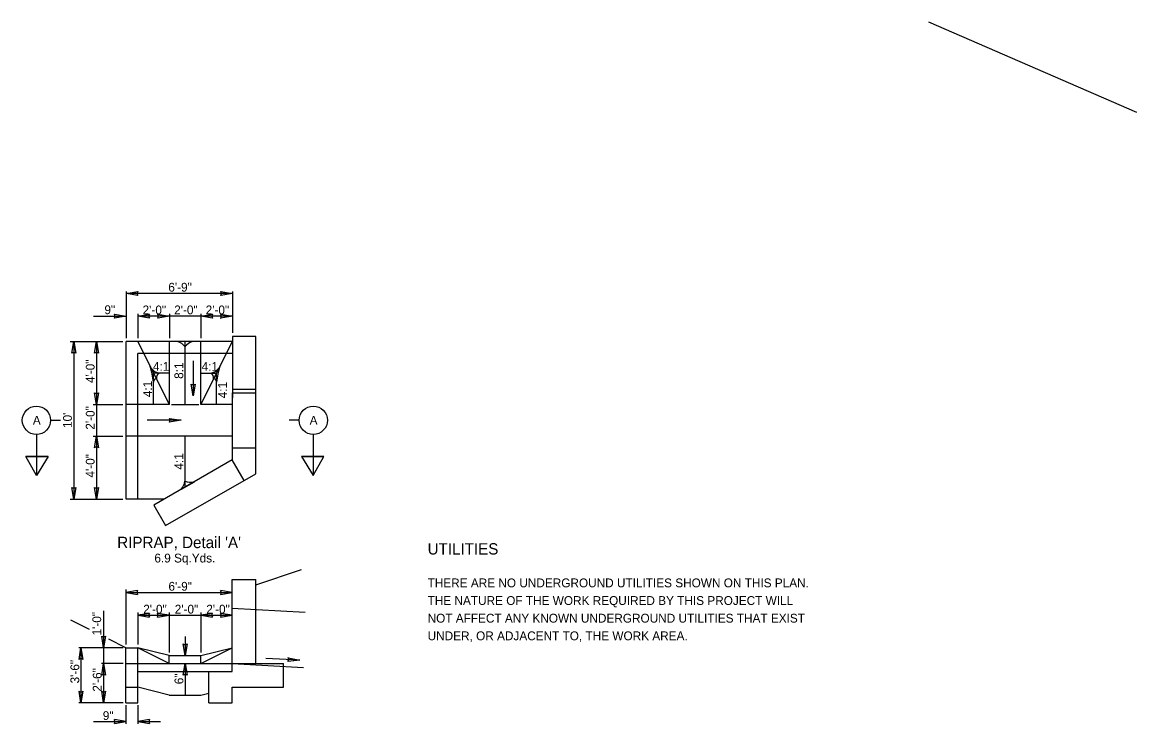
# Model space of a CAD drawing. Extents: x -30 to 76, y -31 to 50.
# Drawn here: x -18.16 to -0.47, y 38.43 to 49.56 of the extents above; entities that cross this region are included whole.
import ezdxf

# ---------------------------------------------------------------- set-up
doc = ezdxf.new("R2010")
doc.units = 0
for name, color, linetype in [('BR_P_Gen_Text', 7, 'Continuous'), ('Default', 7, 'Continuous'), ('DR_Gutter', 7, 'Continuous'), ('DR_P_Culvert', 7, 'Continuous'), ('DR_P_Headwall', 7, 'Continuous'), ('DT_P_Slope_Break_Line', 7, 'Continuous'), ('GK_Drainage_Nodes', 7, 'Continuous'), ('SH_Data', 7, 'Continuous'), ('SH_Text', 7, 'Continuous'), ('TX_X_1', 7, 'Continuous'), ('XS_P_Finished_Grade', 7, 'Continuous')]:
    doc.layers.add(name, color=color, linetype=linetype)

msp = doc.modelspace()

# ---------------------------------------------------------------- linework, layer by layer
at = {"layer": 'BR_P_Gen_Text'}
for p, q in [((-17.713, 43.246), (-17.558, 43.246)), ((-13.767, 43.246), (-13.923, 43.246)), ((-17.938, 43.021), (-17.938, 42.37)), ((-13.542, 43.021), (-13.542, 42.37)), ((-18.104, 42.67), (-17.749, 42.67)), ((-17.938, 42.37), (-18.104, 42.67)), ((-18.104, 42.67), (-17.749, 42.67)), ((-17.749, 42.67), (-18.104, 42.67)), ((-18.104, 42.67), (-17.749, 42.67)), ((-17.938, 42.37), (-18.104, 42.67)), ((-17.749, 42.67), (-17.938, 42.37)), ((-17.749, 42.67), (-17.938, 42.37)), ((-13.376, 42.67), (-13.731, 42.67)), ((-13.731, 42.67), (-13.542, 42.37)), ((-13.376, 42.67), (-13.731, 42.67)), ((-13.731, 42.67), (-13.376, 42.67)), ((-13.376, 42.67), (-13.731, 42.67)), ((-13.731, 42.67), (-13.542, 42.37)), ((-13.542, 42.37), (-13.376, 42.67)), ((-13.542, 42.37), (-13.376, 42.67))]:
    msp.add_line(p, q, dxfattribs=at)
for centre in [(-17.938, 43.246), (-13.542, 43.246)]:
    msp.add_circle(centre, 0.225, dxfattribs=at)
at = {"layer": 'Default'}
for p, q in [((-16.515, 45.258), (-16.329, 45.288)), ((-16.33, 45.227), (-16.515, 45.258)), ((-16.33, 45.227), (-16.33, 45.227)), ((-16.329, 45.288), (-16.329, 45.288)), ((-14.825, 45.258), (-15.011, 45.227)), ((-15.011, 45.227), (-15.01, 45.227)), ((-15.01, 45.288), (-15.01, 45.288)), ((-15.01, 45.288), (-14.825, 45.258)), ((-16.515, 44.898), (-16.7, 44.867)), ((-16.7, 44.867), (-16.7, 44.867)), ((-16.699, 44.928), (-16.699, 44.928)), ((-16.699, 44.928), (-16.515, 44.898)), ((-16.329, 44.898), (-16.143, 44.928)), ((-16.144, 44.867), (-16.329, 44.898)), ((-16.143, 44.928), (-16.144, 44.928)), ((-16.144, 44.867), (-16.144, 44.867)), ((-15.827, 44.898), (-16.013, 44.867)), ((-16.013, 44.867), (-16.012, 44.867)), ((-16.012, 44.928), (-16.012, 44.928)), ((-16.012, 44.928), (-15.827, 44.898)), ((-15.327, 44.898), (-15.142, 44.928)), ((-15.142, 44.867), (-15.327, 44.898)), ((-15.142, 44.928), (-15.142, 44.928)), ((-15.142, 44.867), (-15.142, 44.867)), ((-14.827, 44.898), (-15.013, 44.867)), ((-15.013, 44.867), (-15.012, 44.867)), ((-15.012, 44.928), (-15.012, 44.928)), ((-15.012, 44.928), (-14.827, 44.898)), ((-17.375, 44.311), (-17.345, 44.496)), ((-17.345, 44.496), (-17.314, 44.31)), ((-17.015, 44.311), (-16.985, 44.496)), ((-16.985, 44.496), (-16.954, 44.31)), ((-17.375, 44.311), (-17.375, 44.311)), ((-17.314, 44.31), (-17.314, 44.31)), ((-17.015, 44.311), (-17.015, 44.311)), ((-16.954, 44.31), (-16.954, 44.31)), ((-15.451, 43.636), (-15.482, 43.821)), ((-15.482, 43.821), (-15.482, 43.821)), ((-15.42, 43.821), (-15.451, 43.636)), ((-15.42, 43.821), (-15.42, 43.821)), ((-16.985, 43.496), (-17.015, 43.681)), ((-17.015, 43.681), (-17.015, 43.681)), ((-16.954, 43.681), (-16.985, 43.496)), ((-16.954, 43.681), (-16.954, 43.681)), ((-15.642, 43.246), (-15.828, 43.215)), ((-15.828, 43.215), (-15.828, 43.215)), ((-15.827, 43.277), (-15.827, 43.277)), ((-15.827, 43.277), (-15.642, 43.246)), ((-17.015, 42.811), (-16.985, 42.996)), ((-16.985, 42.996), (-16.954, 42.81)), ((-17.015, 42.811), (-17.015, 42.811)), ((-16.954, 42.81), (-16.954, 42.81)), ((-17.345, 41.996), (-17.375, 42.181)), ((-17.375, 42.181), (-17.375, 42.181)), ((-17.314, 42.181), (-17.345, 41.996)), ((-17.314, 42.181), (-17.314, 42.181)), ((-16.985, 41.996), (-17.015, 42.181)), ((-17.015, 42.181), (-17.015, 42.181)), ((-16.954, 42.181), (-16.985, 41.996)), ((-16.954, 42.181), (-16.954, 42.181)), ((-16.333, 40.543), (-16.518, 40.512)), ((-16.333, 40.543), (-16.333, 40.543)), ((-14.828, 40.512), (-15.014, 40.543)), ((-15.014, 40.543), (-15.014, 40.543)), ((-16.518, 40.512), (-16.332, 40.481)), ((-16.332, 40.481), (-16.332, 40.481)), ((-15.013, 40.481), (-14.828, 40.512)), ((-15.013, 40.481), (-15.013, 40.481)), ((-16.145, 40.183), (-16.33, 40.152)), ((-16.145, 40.183), (-16.145, 40.183)), ((-15.83, 40.152), (-16.016, 40.183)), ((-16.016, 40.183), (-16.016, 40.183)), ((-15.145, 40.183), (-15.33, 40.152)), ((-15.145, 40.183), (-15.145, 40.183)), ((-14.828, 40.152), (-15.014, 40.183)), ((-15.014, 40.183), (-15.014, 40.183)), ((-16.33, 40.152), (-16.145, 40.121)), ((-16.145, 40.121), (-16.145, 40.121)), ((-16.015, 40.121), (-15.83, 40.152)), ((-16.015, 40.121), (-16.015, 40.121)), ((-15.33, 40.152), (-15.145, 40.121)), ((-15.145, 40.121), (-15.145, 40.121)), ((-15.013, 40.121), (-14.828, 40.152)), ((-15.013, 40.121), (-15.013, 40.121)), ((-16.871, 39.637), (-16.902, 39.823)), ((-16.902, 39.823), (-16.902, 39.823)), ((-16.84, 39.822), (-16.871, 39.637)), ((-16.84, 39.822), (-16.84, 39.822)), ((-17.261, 39.452), (-17.231, 39.637)), ((-17.231, 39.637), (-17.2, 39.452)), ((-15.578, 39.512), (-15.609, 39.698)), ((-15.609, 39.698), (-15.609, 39.698)), ((-15.547, 39.697), (-15.578, 39.512)), ((-15.547, 39.697), (-15.547, 39.697)), ((-13.94, 39.479), (-13.94, 39.479)), ((-13.94, 39.479), (-13.757, 39.439)), ((-17.261, 39.452), (-17.261, 39.452)), ((-17.2, 39.452), (-17.2, 39.452)), ((-16.902, 39.202), (-16.871, 39.387)), ((-16.871, 39.387), (-16.84, 39.202)), ((-15.609, 39.202), (-15.578, 39.387)), ((-15.578, 39.387), (-15.547, 39.202)), ((-13.757, 39.439), (-13.944, 39.418)), ((-13.944, 39.418), (-13.944, 39.418)), ((-16.902, 39.202), (-16.902, 39.202)), ((-16.84, 39.202), (-16.84, 39.202)), ((-15.609, 39.202), (-15.609, 39.202)), ((-15.547, 39.202), (-15.547, 39.202)), ((-17.231, 38.762), (-17.261, 38.948)), ((-17.261, 38.948), (-17.261, 38.948)), ((-17.2, 38.947), (-17.231, 38.762)), ((-17.2, 38.947), (-17.2, 38.947)), ((-16.871, 38.762), (-16.902, 38.948)), ((-16.902, 38.948), (-16.902, 38.948)), ((-16.84, 38.947), (-16.871, 38.762)), ((-16.84, 38.947), (-16.84, 38.947)), ((-16.516, 38.466), (-16.701, 38.497)), ((-16.701, 38.497), (-16.701, 38.497)), ((-16.701, 38.435), (-16.516, 38.466)), ((-16.701, 38.435), (-16.701, 38.435)), ((-16.143, 38.497), (-16.328, 38.466)), ((-16.328, 38.466), (-16.143, 38.435)), ((-16.143, 38.497), (-16.143, 38.497)), ((-16.143, 38.435), (-16.143, 38.435))]:
    msp.add_line(p, q, dxfattribs=at)
for centre, start, end in [((-16.282, 45.257), 146.178, 212.8588), ((-15.057, 45.258), 326.178, 32.8588), ((-16.747, 44.898), 326.178, 32.8588), ((-16.097, 44.897), 146.178, 212.8588), ((-16.059, 44.898), 326.178, 32.8588), ((-15.095, 44.897), 146.178, 212.8588), ((-15.059, 44.898), 326.178, 32.8588), ((-17.345, 44.264), 56.178, 122.8588), ((-16.985, 44.264), 56.178, 122.8588), ((-15.451, 43.868), 236.178, 302.8588), ((-16.984, 43.728), 236.178, 302.8588), ((-15.874, 43.246), 326.178, 32.8588), ((-16.985, 42.764), 56.178, 122.8588), ((-17.344, 42.228), 236.178, 302.8588), ((-16.984, 42.228), 236.178, 302.8588), ((-16.285, 40.513), 147.1412, 213.822), ((-15.06, 40.512), 327.1412, 33.822), ((-16.098, 40.153), 147.1412, 213.822), ((-16.062, 40.152), 327.1412, 33.822), ((-15.098, 40.153), 147.1412, 213.822), ((-15.06, 40.152), 327.1412, 33.822), ((-16.87, 39.869), 236.178, 302.8588), ((-15.578, 39.744), 236.178, 302.8588), ((-17.231, 39.405), 56.178, 122.8588), ((-13.989, 39.452), 323.0985, 29.7792), ((-16.871, 39.155), 56.178, 122.8588), ((-15.579, 39.155), 56.178, 122.8588), ((-17.23, 38.994), 236.178, 302.8588), ((-16.87, 38.994), 236.178, 302.8588), ((-16.748, 38.466), 327.1412, 33.822), ((-16.096, 38.466), 147.1412, 213.822)]:
    msp.add_arc(centre, 0.0563, start, end, dxfattribs=at)
at = {"layer": 'DR_Gutter'}
for p, q in [((-14.827, 44.496), (-16.515, 44.496)), ((-16.515, 41.996), (-16.515, 44.496)), ((-15.827, 43.496), (-16.327, 44.496)), ((-15.827, 43.496), (-15.827, 44.496)), ((-15.327, 43.496), (-15.327, 44.496)), ((-15.327, 43.496), (-14.827, 44.496)), ((-16.327, 41.996), (-16.327, 44.308)), ((-14.827, 44.308), (-16.327, 44.308)), ((-15.827, 43.496), (-16.515, 43.496)), ((-15.794, 43.496), (-15.359, 43.496)), ((-14.827, 43.496), (-15.327, 43.496)), ((-14.827, 42.996), (-16.515, 42.996)), ((-15.905, 41.996), (-16.515, 41.996)), ((-16.516, 39.637), (-16.328, 39.637)), ((-16.516, 39.387), (-16.516, 39.637)), ((-15.828, 39.387), (-16.328, 39.637)), ((-15.828, 39.512), (-16.328, 39.637)), ((-16.328, 39.262), (-16.328, 39.637)), ((-15.328, 39.387), (-14.828, 39.637)), ((-15.328, 39.512), (-14.828, 39.637)), ((-15.828, 39.512), (-15.328, 39.512)), ((-15.828, 39.387), (-15.828, 39.512)), ((-15.328, 39.387), (-15.328, 39.512)), ((-16.516, 38.762), (-16.516, 39.387)), ((-16.516, 39.387), (-14.828, 39.387)), ((-16.328, 39.262), (-15.203, 39.262)), ((-16.328, 38.762), (-16.328, 39.262)), ((-16.516, 39.012), (-16.328, 39.012)), ((-15.828, 38.887), (-16.328, 39.012)), ((-16.516, 38.762), (-16.328, 38.762)), ((-15.828, 38.887), (-15.328, 38.887)), ((-15.328, 38.887), (-15.203, 38.918))]:
    msp.add_line(p, q, dxfattribs=at)
at = {"layer": 'DR_P_Culvert'}
for p, q in [((-14.827, 43.683), (-14.452, 43.683)), ((-14.827, 42.808), (-14.827, 43.683)), ((-14.827, 42.808), (-14.452, 42.808)), ((-14.828, 39.387), (-14.828, 40.263)), ((-14.828, 40.263), (-13.671, 40.201)), ((-14.828, 39.387), (-13.696, 39.326))]:
    msp.add_line(p, q, dxfattribs=at)
at = {"layer": 'DR_P_Headwall'}
for p, q in [((-0.469, 48.128), (-3.771, 49.561)), ((-14.826, 43.741), (-14.451, 43.74)), ((-14.641, 42.291), (-14.828, 42.616)), ((-14.828, 40.721), (-14.453, 40.721)), ((-14.828, 40.263), (-14.828, 40.721)), ((-14.453, 40.243), (-14.453, 40.721)), ((-14.453, 39.387), (-14.453, 40.243)), ((-14.828, 39.387), (-14.016, 39.387)), ((-14.828, 39.262), (-14.828, 39.387)), ((-14.016, 39.344), (-14.016, 39.387)), ((-14.016, 39.012), (-14.016, 39.344)), ((-15.203, 38.762), (-15.203, 39.262)), ((-15.203, 39.262), (-14.828, 39.262)), ((-14.828, 38.762), (-14.828, 39.012)), ((-14.828, 39.012), (-14.016, 39.012)), ((-15.203, 38.762), (-14.828, 38.762))]:
    msp.add_line(p, q, dxfattribs=at)
msp.add_lwpolyline([(-14.453, 44.573), (-14.825, 44.574), (-14.828, 42.616), (-16.074, 41.899), (-15.888, 41.576), (-14.453, 42.399)], close=True, dxfattribs=at)
at = {"layer": 'DT_P_Slope_Break_Line'}
for p, q in [((-15.461, 44.496), (-15.697, 44.496)), ((-15.579, 43.496), (-15.579, 44.496)), ((-16.077, 43.496), (-16.077, 43.996)), ((-15.827, 43.996), (-16.077, 43.996)), ((-15.327, 43.996), (-15.077, 43.996)), ((-15.077, 43.496), (-15.077, 43.996)), ((-15.579, 42.183), (-15.579, 42.996)), ((-15.435, 42.266), (-15.64, 42.148))]:
    msp.add_line(p, q, dxfattribs=at)
for centre, radius, start, end in [((-15.791, 44.236), 0.277, 39.9236, 69.9953), ((-15.367, 44.236), 0.277, 110.0047, 140.0764), ((-15.96, 44.188), 0.195, 206.9477, 261.6468), ((-17.184, 43.75), 1.108, 5.2948, 18.4424), ((-15.198, 44.188), 0.195, 278.3532, 333.0523), ((-13.974, 43.75), 1.108, 161.5576, 174.7052), ((-16.029, 43.85), 0.0518, 95.3314, 178.1507), ((-15.944, 43.916), 0.091, 118.8267, 188.9727), ((-15.214, 43.916), 0.091, 351.0273, 61.1733), ((-15.129, 43.85), 0.0518, 1.8493, 84.6686), ((-15.852, 42.327), 0.277, 319.7568, 349.994), ((-15.483, 42.539), 0.277, 249.8412, 280.0783)]:
    msp.add_arc(centre, radius, start, end, dxfattribs=at)
at = {"layer": 'GK_Drainage_Nodes'}
for p, q in [((-14.83, 43.246), (-14.83, 43.246)), ((-14.83, 43.246), (-14.83, 43.246)), ((-14.83, 43.246), (-14.83, 43.246)), ((-14.83, 43.246), (-14.83, 43.246)), ((-14.83, 43.246), (-14.83, 43.246)), ((-14.455, 43.245), (-14.455, 43.245))]:
    msp.add_line(p, q, dxfattribs=at)
at = {"layer": 'SH_Data'}
for p, q in [((-16.515, 45.288), (-16.515, 44.551)), ((-14.825, 45.258), (-16.515, 45.258)), ((-14.825, 45.288), (-14.825, 44.634)), ((-17.033, 44.898), (-16.515, 44.898)), ((-15.827, 44.898), (-16.329, 44.898)), ((-16.327, 44.934), (-16.327, 44.551)), ((-15.827, 44.934), (-15.827, 44.551)), ((-15.327, 44.898), (-15.827, 44.898)), ((-15.327, 44.934), (-15.327, 44.551)), ((-14.827, 44.898), (-15.327, 44.898)), ((-17.402, 44.496), (-16.566, 44.496)), ((-17.345, 44.496), (-17.345, 41.996)), ((-16.985, 44.496), (-16.985, 43.496)), ((-15.451, 44.188), (-15.451, 43.636)), ((-17.038, 43.496), (-16.566, 43.496)), ((-16.985, 43.496), (-16.985, 42.996)), ((-15.642, 43.246), (-16.182, 43.246)), ((-17.038, 42.996), (-16.566, 42.996)), ((-16.985, 42.996), (-16.985, 41.996)), ((-17.402, 41.996), (-16.566, 41.996)), ((-16.516, 40.562), (-16.516, 39.688)), ((-16.518, 40.512), (-14.828, 40.512)), ((-16.871, 40.223), (-16.871, 39.637)), ((-16.328, 40.198), (-16.328, 39.688)), ((-15.828, 40.198), (-15.828, 39.561)), ((-15.328, 40.198), (-15.328, 39.561)), ((-16.33, 40.152), (-15.83, 40.152)), ((-15.83, 40.152), (-15.33, 40.152)), ((-15.33, 40.152), (-14.828, 40.152)), ((-15.578, 39.813), (-15.578, 39.512)), ((-16.561, 39.637), (-17.267, 39.637)), ((-17.231, 39.637), (-17.231, 38.762)), ((-16.871, 39.637), (-16.871, 39.387)), ((-13.757, 39.439), (-14.297, 39.468)), ((-16.561, 39.387), (-16.904, 39.387)), ((-16.871, 39.387), (-16.871, 38.762)), ((-15.578, 39.387), (-15.578, 38.887)), ((-16.561, 38.762), (-17.267, 38.762)), ((-16.516, 38.724), (-16.516, 38.432)), ((-16.328, 38.724), (-16.328, 38.432)), ((-17.034, 38.466), (-16.516, 38.466)), ((-16.328, 38.466), (-15.969, 38.466))]:
    msp.add_line(p, q, dxfattribs=at)
at = {"layer": 'XS_P_Finished_Grade'}
for p, q in [((-14.453, 40.637), (-13.728, 40.879)), ((-17.093, 39.926), (-17.392, 40.075)), ((-16.516, 39.637), (-16.791, 39.775))]:
    msp.add_line(p, q, dxfattribs=at)

# ---------------------------------------------------------------- texts
at = {"layer": 'BR_P_Gen_Text'}
for p in [(-17.995, 43.176), (-13.6, 43.176)]:
    msp.add_text('A', height=0.14, dxfattribs=at).set_placement(p)
at = {"layer": 'SH_Text'}
for s, height, p in [("RIPRAP, Detail 'A'", 0.18, (-16.655, 41.218)), ('UTILITIES', 0.18, (-11.727, 41.116)), ('THERE ARE NO UNDERGROUND UTILITIES SHOWN ON THIS PLAN.', 0.14, (-11.727, 40.596)), ('THE NATURE OF THE WORK REQUIRED BY THIS PROJECT WILL', 0.14, (-11.727, 40.316)), ('NOT AFFECT ANY KNOWN UNDERGROUND UTILITIES THAT EXIST', 0.14, (-11.727, 40.036)), ('UNDER, OR ADJACENT TO, THE WORK AREA.', 0.14, (-11.727, 39.756))]:
    msp.add_text(s, height=height, dxfattribs=at).set_placement(p)
at = {"layer": 'TX_X_1'}
for s, p in [('6\'-9"', (-15.844, 45.287)), ('9"', (-16.859, 44.93)), ('2\'-0"', (-16.252, 44.927)), ('2\'-0"', (-15.751, 44.927)), ('2\'-0"', (-15.251, 44.927)), ('4:1', (-16.088, 44.031)), ('4:1', (-15.315, 44.031)), ('6.9 Sq.Yds.', (-16.065, 40.99)), ('6\'-9"', (-15.842, 40.542)), ('2\'-0"', (-16.242, 40.179)), ('2\'-0"', (-15.742, 40.179)), ('2\'-0"', (-15.241, 40.179)), ('9"', (-16.884, 38.49))]:
    msp.add_text(s, height=0.14, dxfattribs=at).set_placement(p)
for s, p in [('4\'-0"', (-17.014, 43.837)), ('8:1', (-15.607, 43.903)), ('4:1', (-16.103, 43.613)), ('4:1', (-14.913, 43.595)), ("10'", (-17.376, 43.124)), ('2\'-0"', (-17.014, 43.097)), ('4\'-0"', (-17.014, 42.337)), ('4:1', (-15.608, 42.463)), ('1\'-0"', (-16.91, 39.832)), ('3\'-6"', (-17.258, 39.071)), ('2\'-6"', (-16.903, 38.94)), ('6"', (-15.605, 39.058))]:
    msp.add_text(s, height=0.14, rotation=90, dxfattribs=at).set_placement(p)

doc.saveas('drawing.dxf')
